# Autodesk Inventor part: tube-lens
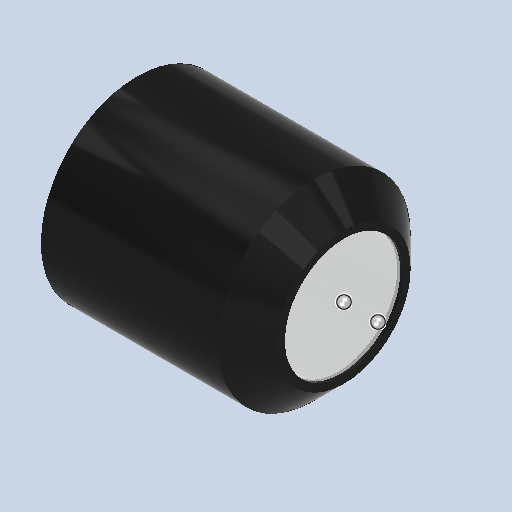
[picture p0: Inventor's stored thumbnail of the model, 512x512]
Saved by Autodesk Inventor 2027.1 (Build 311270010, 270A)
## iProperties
Created: 2026-07
Part Number: tube-lens
Material: Generic
Document SubType Name: Modeling
Designer: dunge
Density: 1 g/cm^3
Appearance: Default
Author: dunge
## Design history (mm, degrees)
derived "scan-lens-sl-simple.ipt"
  workaxis "Work Axis1"
  workpoint "Work Point1"
feature "Solid1::scan-lens-sl-simple.ipt"
tag "TaggingFeature1"
node "Finishes"
body "Solid1"
node "Finish1" dims "Finish1_Area" = 791.30014
node "Finish2" dims "Finish2_Area" = 129.71711
other parameters: "d0" = 16.51, "d4" = 0.508, "LIGHT_RADIUS" = 10.16, "d9" = 135 deg, "d10" = 0.508, "BODY_SIZE" = 35.56, "d12" = 5.08, "d13" = 0.508, "d14" = 0.508, "d15" = 0, "d16" = 0
